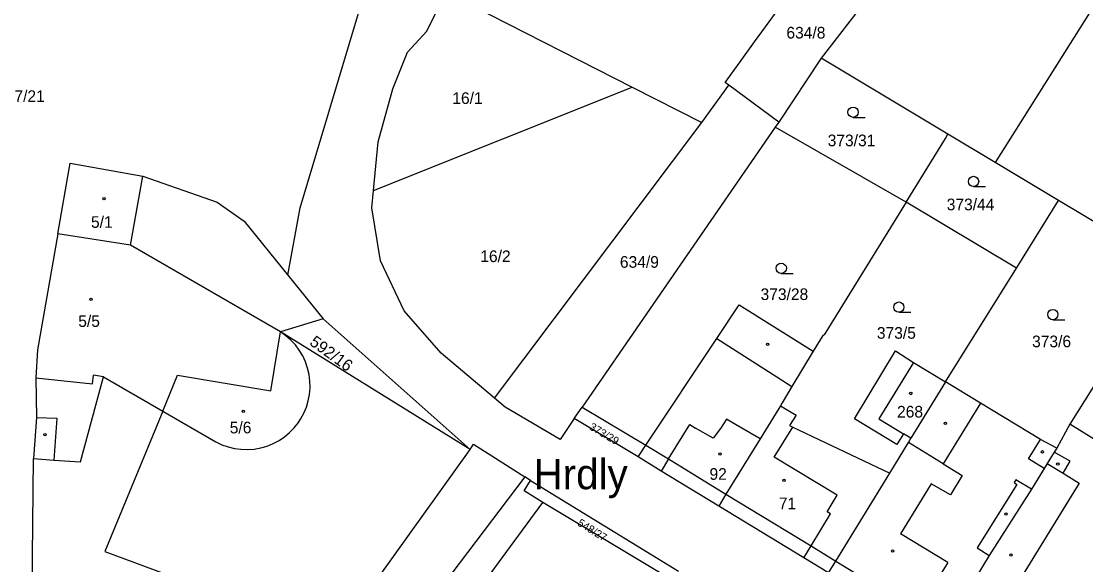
# Model space of a CAD drawing. Extents: x -758582 to -751794, y -998770 to -994350.
# Drawn here: x -754496.6 to -754341.3, y -996932.8 to -996853.5 of the extents above; entities that cross this region are included whole.
import ezdxf

# ---------------------------------------------------------------- set-up
doc = ezdxf.new("R2010")
doc.units = 0
for name, color, linetype in [('Hranice parcel', 7, 'Continuous'), ('Parcelní čísla', 7, 'Continuous'), ('Pop  PČ popisy', 7, 'Continuous'), ('Vnitřní kresba', 7, 'Continuous'), ('Značky budov', 7, 'Continuous'), ('Značky kultur', 7, 'Continuous')]:
    doc.layers.add(name, color=color, linetype=linetype)

msp = doc.modelspace()

# ---------------------------------------------------------------- linework, layer by layer
at = {"layer": 'Hranice parcel'}
for p, q in [((-754329.23, -996833.87), (-754354.52, -996874.08)), ((-754368.1, -996843.52), (-754379.89, -996858.86)), ((-754437.45, -996854.9), (-754434.63, -996849.28)), ((-754430.77, -996851.24), (-754407.49, -996863.07)), ((-754379.89, -996858.86), (-754386.06, -996868.19)), ((-754361.4, -996869.95), (-754379.89, -996858.86)), ((-754397.31, -996868.25), (-754393.39, -996862.8)), ((-754393.39, -996862.8), (-754393.91, -996862.42)), ((-754386.06, -996868.19), (-754393.39, -996862.8)), ((-754445.22, -996878.16), (-754407.49, -996863.07)), ((-754407.49, -996863.07), (-754397.31, -996868.25)), ((-754427.54, -996908.5), (-754397.31, -996868.25)), ((-754386.59, -996868.95), (-754414.77, -996909.79)), ((-754386.06, -996868.19), (-754386.59, -996868.95)), ((-754367.5, -996879.86), (-754386.59, -996868.95)), ((-754367.5, -996879.86), (-754361.78, -996870.56)), ((-754361.78, -996870.56), (-754361.4, -996869.95)), ((-754354.52, -996874.08), (-754361.4, -996869.95)), ((-754445.22, -996878.16), (-754444.54, -996871.05)), ((-754345.27, -996879.63), (-754354.52, -996874.08)), ((-754445.46, -996880.71), (-754445.22, -996878.16)), ((-754367.5, -996879.86), (-754379.44, -996899.26)), ((-754351.41, -996889.5), (-754367.5, -996879.86)), ((-754351.41, -996889.5), (-754345.27, -996879.63)), ((-754333.94, -996886.4), (-754345.27, -996879.63)), ((-754464.08, -996882.64), (-754457.7, -996890.51)), ((-754457.7, -996890.51), (-754452.53, -996896.89)), ((-754361.75, -996906.11), (-754351.41, -996889.5)), ((-754452.53, -996896.89), (-754458.78, -996898.81)), ((-754452.53, -996896.89), (-754431.11, -996915.96)), ((-754431.11, -996915.96), (-754458.78, -996898.81)), ((-754427.54, -996908.5), (-754435.35, -996901.93)), ((-754484.6, -996905.38), (-754475.96, -996910.38)), ((-754361.75, -996906.11), (-754366.8, -996914.31)), ((-754426.01, -996909.79), (-754427.54, -996908.5)), ((-754475.96, -996910.38), (-754468.21, -996914.86)), ((-754415.92, -996911.47), (-754414.77, -996909.79)), ((-754414.77, -996909.79), (-754405.48, -996915.36)), ((-754495.32, -996967.75), (-754494.83, -996917.27)), ((-754422.28, -996920.5), (-754423.15, -996919.95)), ((-754422.28, -996920.5), (-754400.7, -996933.73)), ((-754393.79, -996922.5), (-754394.81, -996924.23)), ((-754401.52, -996935.1), (-754420.48, -996923.69))]:
    msp.add_line(p, q, dxfattribs=at)
for points in [[(-754457.7, -996890.51), (-754455.89, -996880.72), (-754447.09, -996851.31), (-754444.42, -996839.97)], [(-754393.91, -996862.42), (-754391.73, -996859.41), (-754389.61, -996856.49), (-754387.47, -996853.53), (-754385.31, -996850.55), (-754383.17, -996847.6), (-754380.97, -996844.56)], [(-754444.54, -996871.05), (-754442.38, -996863.33), (-754440.26, -996857.97), (-754437.45, -996854.9)], [(-754491.25, -996884.51), (-754489.44, -996874.2), (-754478.86, -996876.09), (-754468.01, -996879.86), (-754464.08, -996882.64)], [(-754435.35, -996901.93), (-754440.73, -996895.76), (-754444.18, -996888.44), (-754445.46, -996880.71)], [(-754491.25, -996884.51), (-754494.23, -996901.43), (-754494.47, -996905.54), (-754494.38, -996911.29), (-754494.83, -996917.27)], [(-754458.78, -996898.81), (-754480.66, -996886.16), (-754491.25, -996884.51)], [(-754405.48, -996915.36), (-754395.14, -996899.77), (-754391.87, -996894.86), (-754381.07, -996901.61)], [(-754475.96, -996910.38), (-754473.79, -996905.11), (-754460.17, -996907.41), (-754458.78, -996898.81)], [(-754468.21, -996914.86), (-754467.34, -996915.28), (-754466.43, -996915.6), (-754465.49, -996915.82), (-754464.54, -996915.95), (-754463.57, -996915.98), (-754462.61, -996915.91), (-754461.66, -996915.74), (-754460.73, -996915.47), (-754459.84, -996915.11), (-754458.98, -996914.66), (-754458.18, -996914.12), (-754457.44, -996913.5), (-754456.77, -996912.81), (-754456.17, -996912.05), (-754455.84, -996911.54), (-754455.38, -996910.69), (-754455, -996909.8), (-754454.73, -996908.88), (-754454.55, -996907.93), (-754454.47, -996906.97), (-754454.48, -996906), (-754454.6, -996905.05), (-754454.82, -996904.1), (-754455.14, -996903.19), (-754455.54, -996902.32), (-754456.04, -996901.49), (-754456.61, -996900.71), (-754457.27, -996900.01), (-754457.99, -996899.37), (-754458.78, -996898.81)], [(-754379.44, -996899.26), (-754379.67, -996899.36), (-754381.07, -996901.61)], [(-754381.07, -996901.61), (-754384.16, -996906.79), (-754385.58, -996909.17), (-754385.83, -996909.58)], [(-754366.8, -996914.31), (-754367.87, -996913.67), (-754368.86, -996915.25), (-754375.06, -996911.49), (-754369.06, -996901.57), (-754366.43, -996903.26), (-754361.75, -996906.11)], [(-754494.83, -996917.27), (-754491.82, -996917.53), (-754487.94, -996917.76), (-754484.6, -996905.38)], [(-754345.53, -996915.8), (-754347.88, -996914.53), (-754356.65, -996909.23), (-754361.75, -996906.11)], [(-754339.35, -996905.46), (-754343.64, -996912.29), (-754345.53, -996915.8)], [(-754385.83, -996909.58), (-754386.07, -996909.99), (-754388.81, -996914.43), (-754393.79, -996922.5)], [(-754385.83, -996909.58), (-754383.57, -996910.97), (-754384.5, -996912.45), (-754384.04, -996912.7), (-754369.89, -996919.43)], [(-754475.96, -996910.38), (-754484.38, -996930.86), (-754475.75, -996934.09), (-754481.31, -996949.73), (-754495.32, -996967.75)], [(-754415.92, -996911.47), (-754417.98, -996914.52), (-754426.01, -996909.79)], [(-754394.81, -996924.23), (-754403.25, -996919.14), (-754406.59, -996917.07), (-754415.92, -996911.47)], [(-754431.11, -996915.96), (-754430.62, -996915.21), (-754423.15, -996919.95)], [(-754405.48, -996915.36), (-754402.15, -996917.35), (-754393.79, -996922.5)], [(-754369.89, -996919.43), (-754367.18, -996914.94), (-754366.8, -996914.31)], [(-754345.53, -996915.8), (-754345.9, -996916.39), (-754346.91, -996918.02), (-754347.35, -996918.73), (-754349.19, -996921.79), (-754355.4, -996931.43), (-754357.5, -996934.88), (-754361.81, -996941.97), (-754362.79, -996943.71)], [(-754521.77, -997040.26), (-754484.43, -996990.49), (-754431.11, -996915.96)], [(-754423.15, -996919.95), (-754446.99, -996951.48), (-754477.33, -996995.8), (-754522.5, -997062.87)], [(-754378.83, -996933.97), (-754377.74, -996932.26), (-754369.89, -996919.43)], [(-754420.48, -996923.69), (-754423.21, -996922), (-754422.28, -996920.5)], [(-754452.71, -996968.39), (-754431.57, -996938.85), (-754426.99, -996932.52), (-754420.48, -996923.69)], [(-754378.83, -996933.97), (-754382.41, -996931.81), (-754394.81, -996924.23)]]:
    msp.add_lwpolyline(points, dxfattribs=at)
at = {"layer": 'Vnitřní kresba'}
for p, q in [((-754480.66, -996886.16), (-754478.86, -996876.09)), ((-754395.14, -996899.77), (-754386.39, -996905.37)), ((-754366.43, -996903.26), (-754371.47, -996911.52)), ((-754494.47, -996905.54), (-754486.22, -996906.4)), ((-754486.22, -996906.4), (-754486.06, -996905.13)), ((-754484.6, -996905.38), (-754486.06, -996905.13)), ((-754386.39, -996905.37), (-754384.16, -996906.79)), ((-754356.65, -996909.23), (-754362.09, -996918.06)), ((-754494.38, -996911.29), (-754491.41, -996911.39)), ((-754491.41, -996911.39), (-754491.82, -996917.53)), ((-754402.15, -996917.35), (-754399.05, -996912.32)), ((-754399.05, -996912.32), (-754398.21, -996912.84)), ((-754393.71, -996911.54), (-754394.6, -996912.91)), ((-754393, -996911.99), (-754393.71, -996911.54)), ((-754388.81, -996914.43), (-754393, -996911.99)), ((-754386.74, -996917.11), (-754384.04, -996912.7)), ((-754371.47, -996911.52), (-754367.87, -996913.67)), ((-754339.02, -996915.15), (-754343.64, -996912.29)), ((-754395.64, -996914.32), (-754398.21, -996912.84)), ((-754394.6, -996912.91), (-754395.64, -996914.32)), ((-754406.59, -996917.07), (-754405.48, -996915.36)), ((-754362.09, -996918.06), (-754367.18, -996914.94)), ((-754349.64, -996917.33), (-754347.88, -996914.53)), ((-754402.15, -996917.35), (-754403.25, -996919.14)), ((-754377.57, -996922.66), (-754386.74, -996917.11)), ((-754347.35, -996918.73), (-754349.64, -996917.33)), ((-754343.55, -996917.68), (-754345.9, -996916.39)), ((-754362.09, -996918.06), (-754359.34, -996919.76)), ((-754346.91, -996918.02), (-754344.58, -996919.44)), ((-754344.58, -996919.44), (-754343.55, -996917.68)), ((-754359.34, -996919.76), (-754361.05, -996922.57)), ((-754351.5, -996920.38), (-754351.76, -996920.81)), ((-754349.19, -996921.79), (-754351.5, -996920.38)), ((-754344.58, -996919.44), (-754342.24, -996920.87)), ((-754363.83, -996920.99), (-754368.33, -996928.3)), ((-754361.05, -996922.57), (-754363.83, -996920.99)), ((-754351.33, -996921.07), (-754357.13, -996930.33)), ((-754342.24, -996920.87), (-754352.68, -996937.8)), ((-754351.76, -996920.81), (-754351.33, -996921.07)), ((-754393.79, -996922.5), (-754381.38, -996930.05)), ((-754379.01, -996925.08), (-754377.57, -996922.66)), ((-754378.53, -996925.39), (-754379.01, -996925.08)), ((-754381.38, -996930.05), (-754378.53, -996925.39)), ((-754361.44, -996932.48), (-754368.33, -996928.3)), ((-754382.41, -996931.81), (-754381.38, -996930.05)), ((-754381.38, -996930.05), (-754377.74, -996932.26)), ((-754357.13, -996930.33), (-754355.4, -996931.43)), ((-754377.74, -996932.26), (-754365.71, -996939.59)), ((-754361.44, -996932.48), (-754362.56, -996934.29))]:
    msp.add_line(p, q, dxfattribs=at)
at = {"layer": 'Značky budov'}
for centre in [(-754484.54, -996879.38), (-754486.41, -996894.04), (-754387.72, -996900.61), (-754366.82, -996907.8), (-754464.2, -996910.4), (-754361.77, -996912.14), (-754493.14, -996913.82), (-754394.67, -996916.65), (-754347.62, -996916.32), (-754345.37, -996918.11), (-754385.33, -996920.47), (-754352.94, -996925.41), (-754369.48, -996930.79), (-754352.21, -996931.38)]:
    msp.add_circle(centre, 0.175, dxfattribs=at)
at = {"layer": 'Značky kultur'}
for p, q in [((-754375.25, -996867.5), (-754373.5, -996867.5)), ((-754357.67, -996877.6), (-754355.92, -996877.6)), ((-754385.72, -996890.28), (-754383.97, -996890.28)), ((-754368.57, -996895.94), (-754366.82, -996895.94)), ((-754346.1, -996897.04), (-754344.35, -996897.04))]:
    msp.add_line(p, q, dxfattribs=at)
for centre in [(-754375.25, -996866.75), (-754357.67, -996876.85), (-754385.72, -996889.53), (-754368.57, -996895.19), (-754346.1, -996896.29)]:
    msp.add_circle(centre, 0.75, dxfattribs=at)

# ---------------------------------------------------------------- texts
at = {"layer": 'Parcelní čísla'}
for s, p in [('634/8', (-754384.97, -996855.99)), ('577/21', (-754500.12, -996865.25)), ('16/1', (-754433.71, -996865.54)), ('373/31', (-754378.95, -996871.71)), ('373/44', (-754361.58, -996881.06)), ('5/1', (-754486.42, -996883.62)), ('16/2', (-754429.63, -996888.62)), ('634/9', (-754409.26, -996889.45)), ('373/28', (-754388.74, -996894.16)), ('5/5', (-754488.28, -996898.08)), ('373/5', (-754371.77, -996899.81)), ('373/6', (-754349.13, -996901.05)), ('268', (-754368.83, -996911.31)), ('5/6', (-754466.18, -996913.62)), ('92', (-754396.19, -996920.4)), ('71', (-754386.07, -996924.69))]:
    msp.add_text(s, height=1.7, dxfattribs=at).set_placement(p)
for s, height, rotation, p in [('592/16', 1.7, 324, (-754454.66, -996900.6)), ('373/29', 1.14, 329, (-754413.83, -996912.97)), ('548/27', 1.14, 328, (-754415.56, -996926.98))]:
    msp.add_text(s, height=height, rotation=rotation, dxfattribs=at).set_placement(p)
at = {"layer": 'Pop  PČ popisy'}
msp.add_text('Hrdly', height=4.4, dxfattribs=at).set_placement((-754421.85, -996921.77))

doc.saveas('drawing.dxf')
